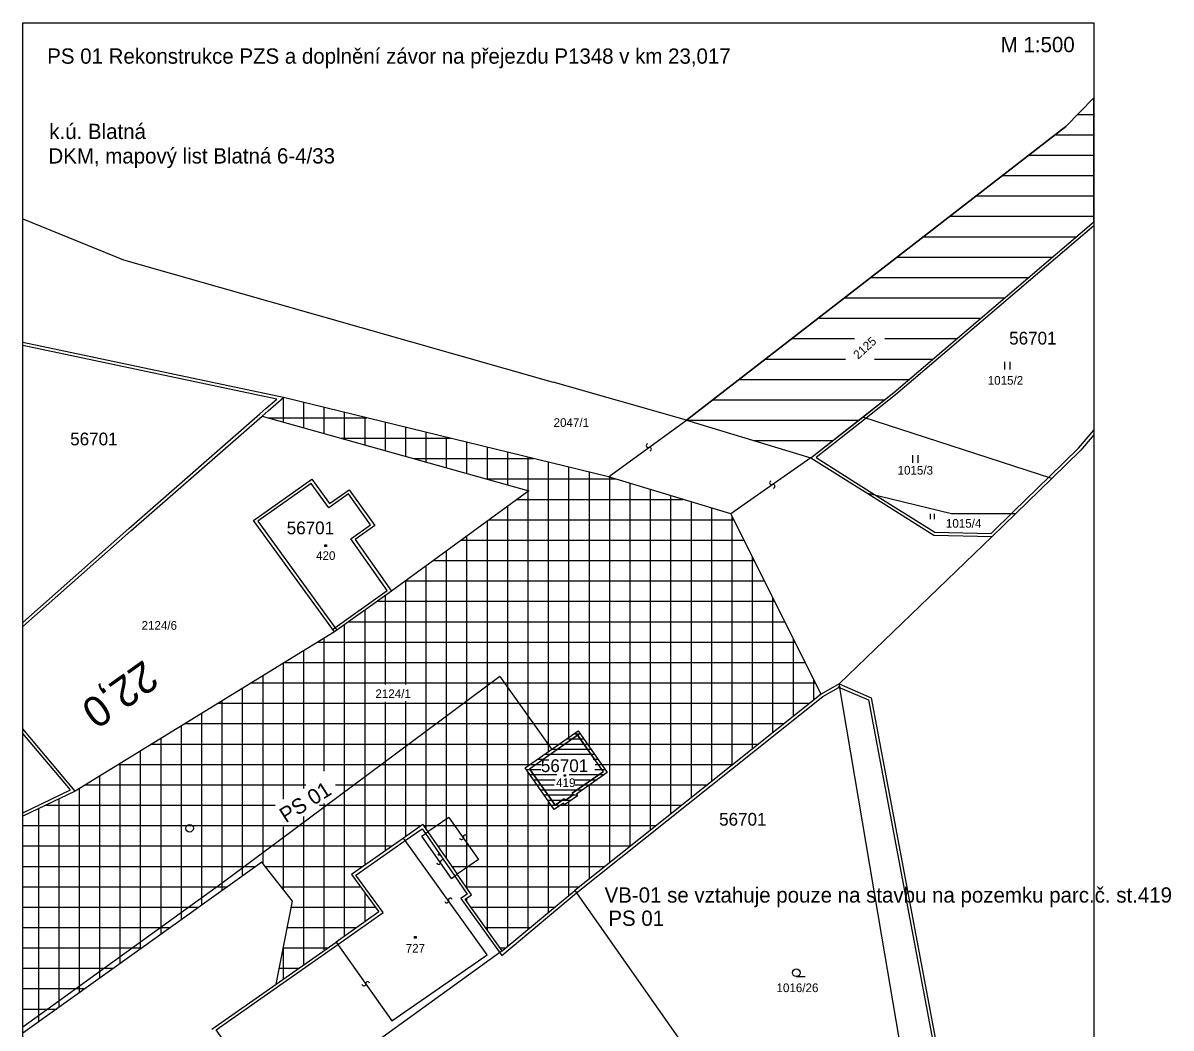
# Model space of a CAD drawing. Extents: x -792659 to -786947, y -1118170 to -1109641.
# Drawn here: x -792087.9 to -791975.3, y -1109739.2 to -1109640.6 of the extents above; entities that cross this region are included whole.
import ezdxf

# ---------------------------------------------------------------- set-up
doc = ezdxf.new("R2010")
doc.units = 0
doc.layers.add('1', color=7, linetype='Continuous')

# ---------------------------------------------------------------- blocks, each defined once
blk = doc.blocks.new('Z4023')
at = {"layer": '1'}
for p, q in [((-0.1, 0.1), (0.2, 0.1)), ((-0.1, -0.2), (-0.1, 0.1)), ((0.2, 0.1), (0.2, -0.2)), ((0.2, -0.2), (-0.1, -0.2))]:
    blk.add_line(p, q, dxfattribs=at)
blk = doc.blocks.new('Z30603')
at = {"layer": '1'}
for p, q in [((-0.5, 0), (-0.5, 1.5)), ((0.5, 1.5), (0.5, 0))]:
    blk.add_line(p, q, dxfattribs=at)
blk = doc.blocks.new('Z30403')
at = {"layer": '1'}
blk.add_line((0, 0), (1.75, 0), dxfattribs=at)
blk.add_circle((0, 0.75), 0.75, dxfattribs=at)

msp = doc.modelspace()

# ---------------------------------------------------------------- linework, layer by layer
at = {"layer": '1'}
for p, q in [((-791985.62, -1109650.78), (-791982.87, -1109647.98)), ((-791985.62, -1109650.78), (-791982.87, -1109647.98)), ((-791984.45, -1109649.59), (-791982.87, -1109649.59)), ((-792022.82, -1109679.59), (-791985.62, -1109650.78)), ((-792022.82, -1109679.59), (-791985.62, -1109650.78)), ((-791986.67, -1109651.59), (-791982.87, -1109651.59)), ((-791989.25, -1109653.59), (-791982.87, -1109653.59)), ((-791991.83, -1109655.59), (-791982.87, -1109655.59)), ((-791994.41, -1109657.59), (-791982.87, -1109657.59)), ((-792087.87, -1109659.83), (-792078.02, -1109663.86)), ((-792002.49, -1109676.88), (-791982.87, -1109660.12)), ((-792002.49, -1109676.88), (-791982.87, -1109660.12)), ((-791997, -1109659.59), (-791982.87, -1109659.59)), ((-791999.58, -1109661.59), (-791984.59, -1109661.59)), ((-792078.02, -1109663.86), (-792035.89, -1109675.87)), ((-792002.16, -1109663.59), (-791986.93, -1109663.59)), ((-792004.74, -1109665.59), (-791989.27, -1109665.59)), ((-792007.33, -1109667.59), (-791991.61, -1109667.59)), ((-792009.91, -1109669.59), (-791993.95, -1109669.59)), ((-792012.49, -1109671.59), (-792006.33, -1109671.59)), ((-792003.35, -1109671.59), (-791996.3, -1109671.59)), ((-792062.33, -1109677.36), (-792087.87, -1109671.97)), ((-792015.07, -1109673.59), (-792007.22, -1109673.59)), ((-792004.36, -1109673.59), (-791998.64, -1109673.59)), ((-792022.82, -1109679.59), (-792035.89, -1109675.87)), ((-792017.66, -1109675.59), (-792000.98, -1109675.59)), ((-792063.84, -1109678.68), (-792062.33, -1109677.36)), ((-792030.44, -1109685.15), (-792062.33, -1109677.36)), ((-792062.33, -1109677.36), (-792062.33, -1109677.36)), ((-792062.33, -1109679.79), (-792062.33, -1109677.36)), ((-792005.53, -1109679.28), (-792002.49, -1109676.88)), ((-792005.53, -1109679.28), (-792002.49, -1109676.88)), ((-792060.33, -1109680.35), (-792060.33, -1109677.85)), ((-792058.33, -1109680.91), (-792058.33, -1109678.34)), ((-792020.24, -1109677.59), (-792003.39, -1109677.59)), ((-792077.28, -1109690.45), (-792064.43, -1109679.2)), ((-792063.84, -1109678.68), (-792064.43, -1109679.2)), ((-792064.43, -1109679.2), (-792038.26, -1109686.52)), ((-792064.33, -1109679.23), (-792064.33, -1109679.11)), ((-792063.86, -1109679.36), (-792054.14, -1109679.36)), ((-792056.33, -1109681.47), (-792056.33, -1109678.83)), ((-792054.33, -1109682.02), (-792054.33, -1109679.31)), ((-792030.44, -1109685.15), (-792022.82, -1109679.59)), ((-792022.82, -1109679.59), (-792010.6, -1109683.28)), ((-792022.82, -1109679.59), (-792005.92, -1109679.59)), ((-792022.82, -1109679.59), (-792010.6, -1109683.28)), ((-792010.6, -1109683.28), (-792005.53, -1109679.28)), ((-792010.6, -1109683.28), (-792005.53, -1109679.28)), ((-791987, -1109685.32), (-792005.53, -1109679.28)), ((-792052.33, -1109682.58), (-792052.33, -1109679.8)), ((-792050.33, -1109683.14), (-792050.33, -1109680.29)), ((-792048.33, -1109683.7), (-792048.33, -1109680.78)), ((-792056.71, -1109681.36), (-792045.96, -1109681.36)), ((-792046.33, -1109684.26), (-792046.33, -1109681.27)), ((-792044.33, -1109684.82), (-792044.33, -1109681.76)), ((-792016.2, -1109681.59), (-792008.46, -1109681.59)), ((-791982.87, -1109681.03), (-791984.15, -1109682.54)), ((-792042.33, -1109685.38), (-792042.33, -1109682.25)), ((-792040.33, -1109685.94), (-792040.33, -1109682.73)), ((-791984.15, -1109682.54), (-791987, -1109685.32)), ((-792049.56, -1109683.36), (-792037.77, -1109683.36)), ((-792038.33, -1109686.5), (-792038.33, -1109683.22)), ((-792036.33, -1109712.11), (-792036.33, -1109683.71)), ((-792034.33, -1109710.71), (-792034.33, -1109684.2)), ((-792010.6, -1109683.28), (-792018.46, -1109688.78)), ((-792010.6, -1109683.28), (-792005.04, -1109686.79)), ((-792065.26, -1109689.44), (-792059.53, -1109685.37)), ((-792059.53, -1109685.37), (-792057.81, -1109687.78)), ((-792042.41, -1109685.36), (-792029.75, -1109685.36)), ((-792032.33, -1109711.66), (-792032.33, -1109684.69)), ((-792018.46, -1109688.78), (-792030.44, -1109685.15)), ((-792030.33, -1109722.99), (-792030.33, -1109685.18)), ((-791987, -1109685.32), (-791990.54, -1109688.77)), ((-792057.81, -1109687.78), (-792055.88, -1109686.41)), ((-792055.88, -1109686.41), (-792053.36, -1109689.93)), ((-792028.33, -1109721.39), (-792028.33, -1109685.79)), ((-792026.33, -1109719.8), (-792026.33, -1109686.4)), ((-792038.26, -1109686.52), (-792051.73, -1109696.36)), ((-792039.41, -1109687.36), (-792023.15, -1109687.36)), ((-792038.33, -1109713.51), (-792038.33, -1109686.57)), ((-792024.33, -1109718.2), (-792024.33, -1109687)), ((-792022.33, -1109716.61), (-792022.33, -1109687.61)), ((-792005.04, -1109686.79), (-791998.55, -1109690.88)), ((-791996.82, -1109688.79), (-792005.04, -1109686.79)), ((-792040.33, -1109731.21), (-792040.33, -1109688.03)), ((-792020.33, -1109715.02), (-792020.33, -1109688.21)), ((-792057.33, -1109700.37), (-792065.26, -1109689.44)), ((-792042.33, -1109705.45), (-792042.33, -1109689.49)), ((-792042.15, -1109689.36), (-792018.17, -1109689.36)), ((-792009.6, -1109706.46), (-792018.46, -1109688.78)), ((-792018.33, -1109713.42), (-792018.33, -1109689.04)), ((-791990.54, -1109688.77), (-791996.82, -1109688.79)), ((-791990.54, -1109688.77), (-791992.82, -1109691)), ((-792087.87, -1109699.84), (-792077.28, -1109690.45)), ((-792053.36, -1109689.93), (-792055.31, -1109691.31)), ((-792044.33, -1109705.42), (-792044.33, -1109690.95)), ((-791992.82, -1109691), (-792007.85, -1109705.47)), ((-791998.55, -1109690.88), (-791992.82, -1109691)), ((-792055.31, -1109691.31), (-792051.73, -1109696.36)), ((-792044.89, -1109691.36), (-792017.17, -1109691.36)), ((-792046.33, -1109722.62), (-792046.33, -1109692.42)), ((-792016.33, -1109711.83), (-792016.33, -1109693.03)), ((-792048.33, -1109719.73), (-792048.33, -1109693.88)), ((-792047.62, -1109693.36), (-792016.17, -1109693.36)), ((-792050.36, -1109695.36), (-792015.16, -1109695.36)), ((-792050.33, -1109705.53), (-792050.33, -1109695.34)), ((-792051.73, -1109696.36), (-792057.33, -1109700.37)), ((-792053.13, -1109697.36), (-792014.16, -1109697.36)), ((-792052.33, -1109705.53), (-792052.33, -1109696.79)), ((-792014.33, -1109710.23), (-792014.33, -1109697.02)), ((-792054.33, -1109723.23), (-792054.33, -1109698.22)), ((-792056.33, -1109730.21), (-792056.33, -1109699.65)), ((-792055.92, -1109699.36), (-792013.16, -1109699.36)), ((-792057.33, -1109700.37), (-792082.74, -1109715.97)), ((-792058.33, -1109714.02), (-792058.33, -1109700.98)), ((-792012.33, -1109708.64), (-792012.33, -1109701.01)), ((-792060.33, -1109715.72), (-792060.33, -1109702.21)), ((-792058.94, -1109701.36), (-792012.16, -1109701.36)), ((-792062.2, -1109703.36), (-792011.15, -1109703.36)), ((-792062.33, -1109716.76), (-792062.33, -1109703.44)), ((-792041.12, -1109704.75), (-792068.33, -1109725.02)), ((-792065.46, -1109705.36), (-792010.15, -1109705.36)), ((-792064.33, -1109723.08), (-792064.33, -1109704.67)), ((-792044.33, -1109725.51), (-792044.33, -1109705.29)), ((-792042.33, -1109729.62), (-792042.33, -1109705.03)), ((-792041.12, -1109704.75), (-792036.02, -1109711.9)), ((-792010.33, -1109707.04), (-792010.33, -1109705)), ((-792007.85, -1109705.47), (-792009.6, -1109706.46)), ((-792003.64, -1109730.21), (-792007.85, -1109705.47)), ((-792007.85, -1109705.47), (-792004.71, -1109706.83)), ((-792066.33, -1109724.29), (-792066.33, -1109705.9)), ((-792009.6, -1109706.46), (-792033.77, -1109725.73)), ((-792068.72, -1109707.36), (-792010.73, -1109707.36)), ((-792068.33, -1109725.73), (-792068.33, -1109707.12)), ((-792052.33, -1109721.83), (-792052.33, -1109707.23)), ((-792050.33, -1109720.43), (-792050.33, -1109707.17)), ((-792004.71, -1109706.83), (-791989.2, -1109789.12)), ((-792070.33, -1109727.16), (-792070.33, -1109708.35)), ((-792082.74, -1109715.97), (-792087.87, -1109709.88)), ((-792072.33, -1109728.59), (-792072.33, -1109709.58)), ((-792071.97, -1109709.36), (-792013.24, -1109709.36)), ((-792038.61, -1109713.71), (-792033.44, -1109710.08)), ((-792033.44, -1109710.08), (-792030.57, -1109714.17)), ((-792074.33, -1109730.03), (-792074.33, -1109710.81)), ((-792038.19, -1109713.78), (-792033.5, -1109710.47)), ((-792034.55, -1109710.86), (-792032.89, -1109710.86)), ((-792033.84, -1109710.36), (-792033.24, -1109710.36)), ((-792033.5, -1109710.47), (-792030.99, -1109714.09)), ((-792076.33, -1109731.46), (-792076.33, -1109712.03)), ((-792075.23, -1109711.36), (-792035.26, -1109711.36)), ((-792036.69, -1109712.36), (-792031.84, -1109712.36)), ((-792035.97, -1109711.86), (-792032.19, -1109711.86)), ((-792035.26, -1109711.36), (-792032.54, -1109711.36)), ((-792032.54, -1109711.36), (-792015.75, -1109711.36)), ((-792078.49, -1109713.36), (-792038.11, -1109713.36)), ((-792078.33, -1109732.89), (-792078.33, -1109713.26)), ((-792038.11, -1109713.36), (-792037.03, -1109713.36)), ((-792037.4, -1109712.86), (-792036.72, -1109712.86)), ((-792031.95, -1109712.86), (-792031.49, -1109712.86)), ((-792031.75, -1109713.36), (-792031.14, -1109713.36)), ((-792031.14, -1109713.36), (-792018.26, -1109713.36)), ((-792080.33, -1109734.33), (-792080.33, -1109714.49)), ((-792035.77, -1109717.77), (-792038.61, -1109713.71)), ((-792038.51, -1109713.86), (-792037.09, -1109713.86)), ((-792038.33, -1109729.54), (-792038.33, -1109714.11)), ((-792038.19, -1109713.78), (-792035.69, -1109717.35)), ((-792038.16, -1109714.36), (-792035.52, -1109714.36)), ((-792034.31, -1109714.36), (-792030.84, -1109714.36)), ((-792034.02, -1109716.19), (-792030.99, -1109714.09)), ((-792030.57, -1109714.17), (-792033.6, -1109716.27)), ((-792031.78, -1109713.86), (-792030.79, -1109713.86)), ((-792082.33, -1109735.76), (-792082.33, -1109715.72)), ((-792081.75, -1109715.36), (-792060.12, -1109715.36)), ((-792057.22, -1109715.36), (-792037.46, -1109715.36)), ((-792037.81, -1109714.86), (-792035.69, -1109714.86)), ((-792037.46, -1109715.36), (-792035.78, -1109715.36)), ((-792033.79, -1109714.86), (-792031.57, -1109714.86)), ((-792033.73, -1109715.36), (-792032.29, -1109715.36)), ((-792032.33, -1109724.58), (-792032.33, -1109715.39)), ((-792032.29, -1109715.36), (-792020.76, -1109715.36)), ((-792082.74, -1109715.97), (-792087.87, -1109718.43)), ((-792084.33, -1109737.19), (-792084.33, -1109716.73)), ((-792037.11, -1109715.86), (-792033.01, -1109715.86)), ((-792036.76, -1109716.36), (-792033.54, -1109716.36)), ((-792036.41, -1109716.86), (-792034.12, -1109716.86)), ((-792035.69, -1109717.35), (-792034.8, -1109716.74)), ((-792034.8, -1109716.74), (-792034.7, -1109716.89)), ((-792033.49, -1109716.43), (-792034.78, -1109717.31)), ((-792034.7, -1109716.89), (-792033.91, -1109716.35)), ((-792033.91, -1109716.35), (-792034.02, -1109716.19)), ((-792033.6, -1109716.27), (-792033.49, -1109716.43)), ((-792086.33, -1109738.63), (-792086.33, -1109717.69)), ((-792085.64, -1109717.36), (-792063.15, -1109717.36)), ((-792058.78, -1109717.36), (-792036.06, -1109717.36)), ((-792058.33, -1109731.61), (-792058.33, -1109717.18)), ((-792036.33, -1109727.87), (-792036.33, -1109716.97)), ((-792036.06, -1109717.36), (-792035.17, -1109717.36)), ((-792034.88, -1109717.16), (-792035.77, -1109717.77)), ((-792035.17, -1109717.36), (-792023.27, -1109717.36)), ((-792034.78, -1109717.31), (-792034.88, -1109717.16)), ((-792034.33, -1109726.2), (-792034.33, -1109717)), ((-792060.33, -1109733.01), (-792060.33, -1109718.48)), ((-792046.11, -1109718.56), (-792048.16, -1109719.98)), ((-792046.11, -1109718.56), (-792043.21, -1109722.69)), ((-792087.87, -1109719.36), (-792048.82, -1109719.36)), ((-792062.33, -1109725.65), (-792062.33, -1109719.49)), ((-792048.66, -1109719.25), (-792050.55, -1109720.58)), ((-792048.75, -1109720.39), (-792048.16, -1109719.98)), ((-792048.66, -1109719.25), (-792048.16, -1109719.98)), ((-792048.58, -1109719.36), (-792025.78, -1109719.36)), ((-792048.16, -1109719.98), (-792045.28, -1109724.14)), ((-792087.87, -1109721.36), (-792051.66, -1109721.36)), ((-792050.55, -1109720.58), (-792055.65, -1109724.16)), ((-792042.35, -1109732.05), (-792050.55, -1109720.58)), ((-792045.84, -1109724.54), (-792048.75, -1109720.39)), ((-792047.2, -1109721.36), (-792028.29, -1109721.36)), ((-792064.44, -1109722.94), (-792087.87, -1109739.73)), ((-792087.87, -1109723.36), (-792065.03, -1109723.36)), ((-792061.45, -1109726.78), (-792064.44, -1109722.94)), ((-792064.11, -1109723.36), (-792054.51, -1109723.36)), ((-792045.82, -1109723.36), (-792030.8, -1109723.36)), ((-792043.21, -1109722.69), (-792045.28, -1109724.14)), ((-792055.65, -1109724.16), (-792052.97, -1109727.83)), ((-792045.84, -1109724.54), (-792045.28, -1109724.14)), ((-792043.88, -1109726.16), (-792045.28, -1109724.14)), ((-792068.33, -1109725.02), (-792087.87, -1109739.13)), ((-792087.87, -1109725.36), (-792067.82, -1109725.36)), ((-792062.56, -1109725.36), (-792054.77, -1109725.36)), ((-792044.43, -1109725.36), (-792033.31, -1109725.36)), ((-792040.87, -1109731.66), (-792033.77, -1109725.73)), ((-792033.77, -1109725.73), (-792023.66, -1109740.13)), ((-792063.04, -1109734.91), (-792061.45, -1109726.78)), ((-792054.33, -1109728.79), (-792054.33, -1109725.97)), ((-792044.51, -1109726.58), (-792043.88, -1109726.16)), ((-792040.87, -1109731.66), (-792044.51, -1109726.58)), ((-792044.33, -1109726.83), (-792044.33, -1109726.46)), ((-792087.87, -1109727.36), (-792070.61, -1109727.36)), ((-792061.56, -1109727.36), (-792053.31, -1109727.36)), ((-792052.97, -1109727.83), (-792057.17, -1109730.8)), ((-792043.95, -1109727.36), (-792035.72, -1109727.36)), ((-792087.87, -1109729.36), (-792073.4, -1109729.36)), ((-792061.96, -1109729.36), (-792055.13, -1109729.36)), ((-792042.52, -1109729.36), (-792038.12, -1109729.36)), ((-791999.09, -1109757.03), (-792003.64, -1109730.21)), ((-792087.87, -1109731.36), (-792076.19, -1109731.36)), ((-792063.04, -1109734.91), (-792057.17, -1109730.8)), ((-792062.35, -1109731.36), (-792057.97, -1109731.36)), ((-792062.33, -1109734.41), (-792062.33, -1109731.28)), ((-792057.17, -1109730.8), (-792051.69, -1109738.52)), ((-792041.08, -1109731.36), (-792040.51, -1109731.36)), ((-792040.87, -1109731.66), (-792054.08, -1109741.21)), ((-792051.69, -1109738.52), (-792042.35, -1109732.05)), ((-792087.87, -1109733.36), (-792078.98, -1109733.36)), ((-792062.74, -1109733.36), (-792060.83, -1109733.36)), ((-792069.34, -1109739.32), (-792063.04, -1109734.91)), ((-792087.87, -1109735.36), (-792081.77, -1109735.36)), ((-792087.87, -1109737.36), (-792084.56, -1109737.36))]:
    msp.add_line(p, q, dxfattribs=at)
for points in [[(-792087.87, -1109640.62), (-791982.87, -1109640.62), (-791982.87, -1109789.12), (-792087.87, -1109789.12)], [(-792022.82, -1109679.59), (-792010.6, -1109683.28), (-792002.49, -1109676.88), (-791982.87, -1109660.12), (-791982.87, -1109647.98), (-791985.62, -1109650.78)], [(-792038.61, -1109713.71), (-792033.44, -1109710.08), (-792030.57, -1109714.17), (-792033.6, -1109716.27), (-792033.49, -1109716.43), (-792034.78, -1109717.31), (-792034.88, -1109717.16), (-792035.77, -1109717.77)]]:
    msp.add_lwpolyline(points, close=True, dxfattribs=at)
for points in [[(-791982.87, -1109660.52), (-792002.3, -1109677.11), (-792005.34, -1109679.52), (-792010.08, -1109683.25), (-792004.88, -1109686.54), (-791998.46, -1109690.58), (-791992.94, -1109690.7), (-791990.75, -1109688.55), (-791987.21, -1109685.1), (-791984.37, -1109682.33), (-791982.87, -1109680.56)], [(-792087.87, -1109699.44), (-792077.48, -1109690.23), (-792064.63, -1109678.98), (-792064.04, -1109678.46), (-792062.98, -1109677.53), (-792087.87, -1109672.27)], [(-792057.51, -1109700.13), (-792052.15, -1109696.29), (-792055.73, -1109691.24), (-792053.78, -1109689.86), (-792055.95, -1109686.83), (-792057.88, -1109688.2), (-792059.6, -1109685.79), (-792064.84, -1109689.51), (-792057.09, -1109700.19)], [(-792019.23, -1109789.12), (-792045.82, -1109755.97), (-792045.22, -1109755.51), (-792051.33, -1109748.15), (-792058.08, -1109744.01), (-792060.08, -1109741.62), (-792064.95, -1109745.07), (-792068.92, -1109739.39), (-792057, -1109731.04), (-792052.55, -1109727.9), (-792055.23, -1109724.23), (-792050.38, -1109720.82), (-792048.74, -1109719.67), (-792048.41, -1109720.15), (-792045.53, -1109724.31), (-792044.3, -1109726.08), (-792044.94, -1109726.5), (-792040.93, -1109732.1), (-792033.58, -1109725.96), (-792009.43, -1109706.71), (-792007.7, -1109705.73)], [(-792007.97, -1109705.75), (-792004.97, -1109707.04), (-791989.5, -1109789.12)], [(-792087.87, -1109718.1), (-792083.22, -1109715.87), (-792087.87, -1109710.34)], [(-792033.69, -1109710.25), (-792030.99, -1109714.09), (-792034.02, -1109716.19), (-792033.91, -1109716.35), (-792034.7, -1109716.89), (-792034.8, -1109716.74), (-792035.69, -1109717.35), (-792038.19, -1109713.78), (-792033.27, -1109710.33)]]:
    msp.add_lwpolyline(points, dxfattribs=at)
msp.add_circle((-792071.53, -1109719.62), 0.375, dxfattribs=at)
for centre, start, end in [((-792026.57, -1109682.09), 111.4312, 291.4312), ((-792026.43, -1109682.43), 291.4312, 111.4312), ((-792014.47, -1109685.74), 111.4312, 291.4312), ((-792014.33, -1109686.08), 291.4312, 111.4312), ((-792044.87, -1109720.55), 191.6251, 11.6251), ((-792044.5, -1109720.47), 11.6251, 191.6251), ((-792047.1, -1109722.98), 189.5066, 9.5066), ((-792046.73, -1109722.92), 9.5066, 189.5066), ((-792046.33, -1109726.76), 196.0419, 16.0418), ((-792045.97, -1109726.66), 16.0419, 196.0419), ((-792054.44, -1109734.9), 187.2854, 7.2854), ((-792054.07, -1109734.86), 7.2854, 187.2854)]:
    msp.add_arc(centre, 0.188, start, end, dxfattribs=at)

# ---------------------------------------------------------------- block references
for name, p, xscale, yscale in [('Z30603', (-791991.34, -1109674.62), 0.4999988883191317, 0.4999988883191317), ('Z30603', (-792000.36, -1109683.77), 0.4999988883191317, 0.4999988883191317), ('Z30603', (-791998.71, -1109689.29), 0.34999922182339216, 0.34999922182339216), ('Z4023', (-792058.21, -1109691.88), 0.4999988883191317, 0.4999988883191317), ('Z4023', (-792034.76, -1109714.42), 0.4999988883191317, 0.4999988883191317), ('Z4023', (-792047.08, -1109722.17), 0.4999988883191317, 0.4999988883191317), ('Z4023', (-792049.43, -1109730.3), 0.4999988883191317, 0.4999988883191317), ('Z30403', (-792012.04, -1109734.17), 0.4999988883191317, 0.4999988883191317)]:
    msp.add_blockref(name, p, dxfattribs=dict(at, xscale=xscale, yscale=yscale))

# ---------------------------------------------------------------- texts
for s, height, p in [('M 1:500', 1.5, (-791991.99, -1109643.49)), ('PS 01 Rekonstrukce PZS a doplnění závor na přejezdu P1348 v km 23,017', 1.5, (-792085.49, -1109644.62)), ('k.ú. Blatná', 1.5, (-792085.29, -1109652.01)), ('DKM, mapový list Blatná 6-4/33', 1.5, (-792085.37, -1109654.41)), ('56701', 1.25, (-791991.17, -1109672.17)), ('1015/2', 0.85, (-791993.27, -1109676.11)), ('2047/1', 0.85, (-792035.84, -1109680.25)), ('56701', 1.25, (-792083.24, -1109682.06)), ('56701', 1.25, (-792062.01, -1109690.78)), ('1015/4', 0.85, (-791997.37, -1109690.14)), ('420', 0.85, (-792059.13, -1109693.3)), ('2124/6', 0.85, (-792076.24, -1109700.15)), ('2124/1', 0.85, (-792053.31, -1109706.85)), ('56701', 1.25, (-792037.09, -1109714.11)), ('419', 0.85, (-792035.59, -1109715.58)), ('56701', 1.25, (-792019.61, -1109719.37)), ('VB-01 se vztahuje pouze na stavbu na pozemku parc.č. st.419', 1.5, (-792030.84, -1109726.92)), ('PS 01', 1.5, (-792030.47, -1109729.2)), ('727', 0.85, (-792050.34, -1109731.82)), ('1016/26', 0.85, (-792013.98, -1109735.7))]:
    msp.add_text(s, height=height, dxfattribs=at).set_placement(p)
for s, height, rotation, p in [('2125', 0.85, 42.0722, (-792005.98, -1109673.66)), ('1015/3', 0.85, 359.7791, (-792002.11, -1109684.92)), ('22,0', 3, 215.3609, (-792076.02, -1109703.03)), ('PS 01', 1.5, 32.364, (-792062.1, -1109719.15))]:
    msp.add_text(s, height=height, rotation=rotation, dxfattribs=at).set_placement(p)

doc.saveas('drawing.dxf')
